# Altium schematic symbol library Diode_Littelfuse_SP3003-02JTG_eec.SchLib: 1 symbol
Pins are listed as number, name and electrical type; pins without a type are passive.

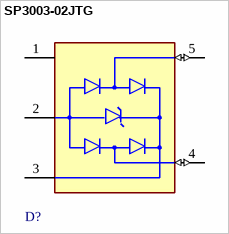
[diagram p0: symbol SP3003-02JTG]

## SP3003-02JTG
designator D?  (value not drawn)
pins: 1 NC, 2 GND (power), 3 VCC (power), 4 I/O2 (io), 5 I/O1 (io)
